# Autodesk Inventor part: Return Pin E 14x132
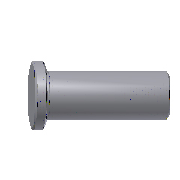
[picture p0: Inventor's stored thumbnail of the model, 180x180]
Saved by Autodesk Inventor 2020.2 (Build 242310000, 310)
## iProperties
Manager: www.cadconsulting.pl
Company: Fabian Stasiak CAD Consulting
Created: 2014-02
Part Number: Return Pin E 14x132
Material: SUJ 2
Description: Return Pin
Document SubType Name: Modeling
Designer: F.Stasiak
Standard Revision: 1
Manufacturer: DME
Language: pl-PL
Size Designation: 14x132
Categories: <MemberInstance><Categories><Category DisplayName="Forma wtryskowa" InternalName="349578f2-f4d4-4954-8c09-8e99297a61c0" Mnemonic="MOLD"><Category DisplayName="K
Mass: 6.63789 g
Surface Area: 25.7048 cm^2
Volume: 6.63789 cm^3
Density: 7.85 g/cm^3
Appearance: Aluminium - ciemne
Catalog Web Link: www.expertbooks.pl
IsCustomPart: 1
Author: F.Stasiak
Subject: Zbiór ćwiczeń. Autodesk Inventor 2020. Kurs Professional
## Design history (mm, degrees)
sketch "Sketch1"
  geometry: L1 (0, -15)-(0, 62) reference; L2 (0, -4)-(9.5, -4); L3 (9.5, -4)-(9.5, 0); L4 (9.5, 0)-(7, 0); L5 (7, 0)-(7, 128); L6 (7, 128)-(0, 128); L7 (0, 128)-(0, -4); 1 further point
  constraints: 12 end point, 3 perpendicular, 2 parallel, 2 point on line, 1 collinear, 1 horizontal alignment
  dimensions: "d28" = 4 distance between parallel lines of L2 L4 (= H_); "d29" = 19 diameter of L3 L1 (= D); "d31" = 14 diameter of L5 L1 (= d_); "d33" = 132 distance between parallel lines of L2 L6 (= L)
revolve "Revolution1" sketch "Sketch1" stored, may be unused: angle "d41" = 90 deg
sketch "Sketch2"
  geometry: L1 (7, 128)-(7, 0) reference; L2 (-7, 0)-(7, 0) reference; L3 (7, 0)-(6.8, 0); L4 (6.5, 0.3)-(6.5, 0.9); L5 (6.8, 1.2)-(7, 1.2); L6 (7, 1.2)-(7, 0); L7 (0, -10.275)-(0, 61.212) reference; A1 r 0.3 centre (6.8, 0.9) between (6.8, 1.2) and (6.5, 0.9); A2 r 0.3 centre (6.8, 0.3) between (6.5, 0.3) and (6.8, 0); 1 further point
  constraints: 8 end point, 4 point on circle, 4 tangent, 2 centre point, 2 parallel, 1 equal radius, 1 horizontal, 1 perpendicular
  dimensions: "d45" = 0.3 radius of A1; "d46" = 1.2 distance between parallel lines of L2 L5; "d47" = 0.5 distance between parallel lines of L4 L1
revolve "Revolution2" sketch "Sketch2" stored, may be unused: angle "d48" = 90 deg
chamfer "Chamfer1" distance "d49" = 0.5; stored, may be unused: second distance "d50" = 2, angle "d51" = 45 deg
body "Solid1"
other parameters: "d_" = 14 [user parameter; used in 1 equation term], "L" = 132 [user parameter; used in 1 equation term], "D" = 19 [user parameter; used in 1 equation term], "H_" = 4 [user parameter; used in 1 equation term], "d44" = 0, "d52" = 0, "d53" = 0
